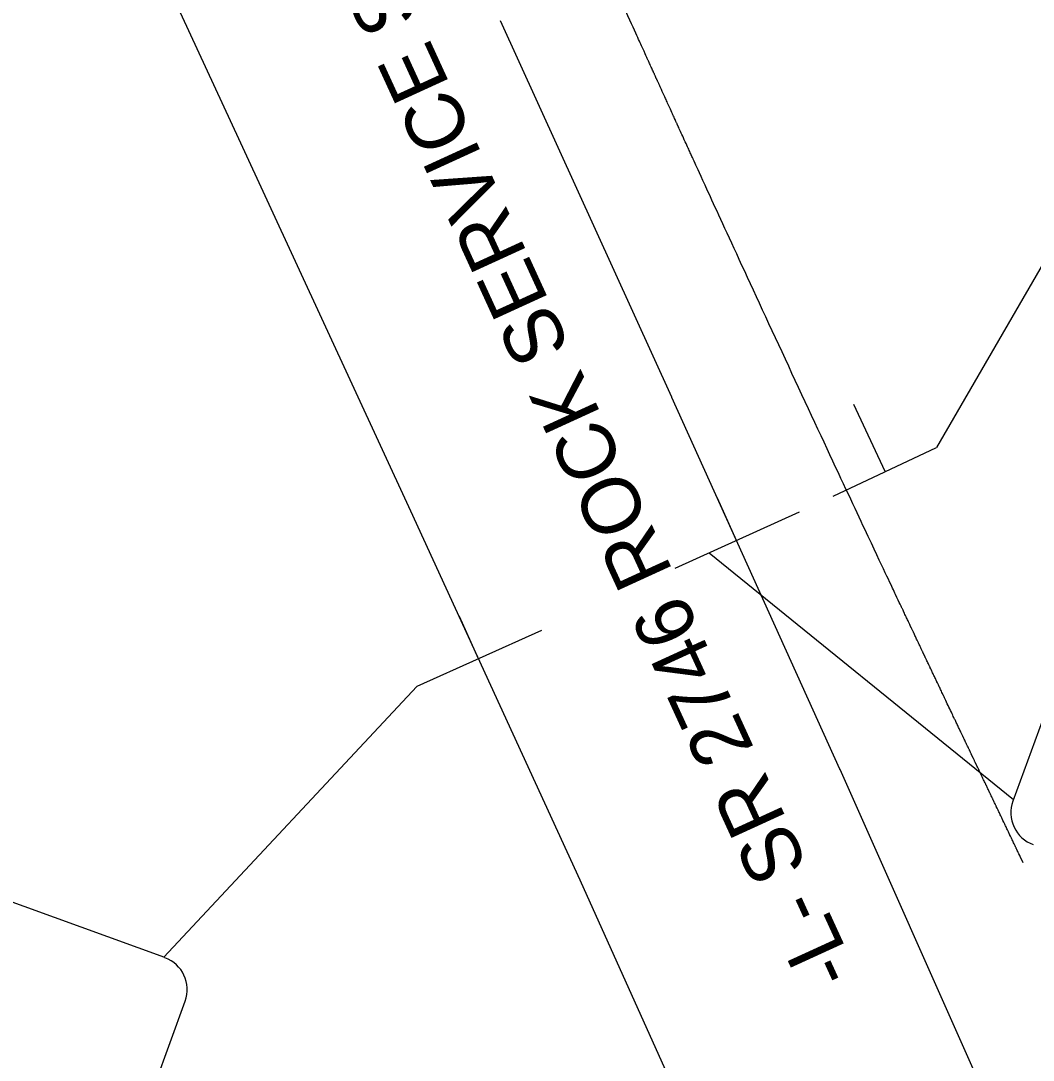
# Model space of a CAD drawing. Extents: x 2096670 to 2098561, y 684033 to 689893.
# Drawn here: x 2097860.5 to 2097982.4, y 685391.2 to 685516.3 of the extents above; entities that cross this region are included whole.
import ezdxf

# ---------------------------------------------------------------- set-up
doc = ezdxf.new("R2010")
doc.units = 0
for name, color, linetype in [('Default', 7, 'Continuous'), ('Exist Sign E Stop Ahead CELL', 7, 'Continuous'), ('Exist Support 1', 7, 'Continuous'), ('Prop DSN Text', 7, 'Continuous'), ('Prop Sign E Signal Light Ahead CELL', 7, 'Continuous'), ('Scratch_Level_4', 7, 'Continuous')]:
    doc.layers.add(name, color=color, linetype=linetype)

msp = doc.modelspace()

# ---------------------------------------------------------------- linework, layer by layer
at = {"layer": 'Exist Sign E Stop Ahead CELL'}
for p, q in [((2097999.49, 685476.17), (2097979.91, 685422.39)), ((2097979.97, 685422.55), (2097943.33, 685452.24)), ((2097908.16, 685436.19), (2097877.73, 685403.6)), ((2097877.84, 685403.56), (2097824.06, 685423.13)), ((2097860.7, 685344.55), (2097880.28, 685398.33))]:
    msp.add_line(p, q, dxfattribs=at)
for centre, start, end in [((2097983.75, 685421), 159.9971, 249.9971), ((2097876.44, 685399.72), 339.9971, 69.9971)]:
    msp.add_arc(centre, 4.08, start, end, dxfattribs=at)
at = {"layer": 'Exist Support 1'}
for p, q in [((2097946.65, 685453.76), (2097944.34, 685458.86)), ((2097954.2, 685457.17), (2097939.21, 685450.4)), ((2097915.59, 685439.55), (2097913.29, 685444.64)), ((2097923.15, 685442.96), (2097908.16, 685436.19))]:
    msp.add_line(p, q, dxfattribs=at)
at = {"layer": 'Prop DSN Text'}
for p, q in [((2097964.54, 685462.07), (2097960.76, 685470.15)), ((2097958.26, 685459.13), (2097970.73, 685464.96))]:
    msp.add_line(p, q, dxfattribs=at)
at = {"layer": 'Prop Sign E Signal Light Ahead CELL'}
msp.add_line((2098020.18, 685550.58), (2097970.73, 685464.96), dxfattribs=at)
at = {"layer": 'Scratch_Level_4'}
for p, q in [((2097938.84, 685471.03), (2097918.24, 685516.35)), ((2097959.08, 685426.23), (2097938.85, 685471.01)), ((2097979.48, 685380.36), (2097959.1, 685426.19))]:
    msp.add_line(p, q, dxfattribs=at)
msp.add_lwpolyline([(2097948.38, 685367.21), (2097927.83, 685412.88), (2097907.44, 685457.32), (2097886.75, 685502.14), (2097865.38, 685548.3)], dxfattribs=at)
for centre, start, end in [((2097933.38, 685468.54), 24.3125, 24.4514), ((2097953.62, 685423.76), 23.9717, 24.3125)]:
    msp.add_arc(centre, 6, start, end, dxfattribs=at)
for points in [[(2097937.71, 685507.83), (2097937.63, 685508), (2097937.51, 685508.26), (2097937.4, 685508.52), (2097937.32, 685508.7), (2097937.28, 685508.78), (2097937.2, 685508.95), (2097937.14, 685509.08), (2097937.08, 685509.21), (2097937.04, 685509.3), (2097937.02, 685509.34), (2097936.99, 685509.41), (2097936.98, 685509.43), (2097936.96, 685509.47), (2097936.95, 685509.49), (2097936.93, 685509.54), (2097936.92, 685509.56), (2097936.9, 685509.6), (2097936.89, 685509.62), (2097936.85, 685509.73), (2097936.81, 685509.82), (2097936.61, 685510.25), (2097936.37, 685510.77), (2097936.1, 685511.37), (2097935.96, 685511.67), (2097935.9, 685511.8), (2097935.86, 685511.89), (2097935.84, 685511.93), (2097935.2, 685513.36), (2097934.57, 685514.74), (2097932.69, 685518.88), (2097928.95, 685527.17), (2097922.74, 685541), (2097916.58, 685554.85), (2097912.91, 685563.18), (2097911.65, 685566.04), (2097911.61, 685566.12), (2097911.53, 685566.3), (2097911.42, 685566.56), (2097911.15, 685567.16), (2097910.92, 685567.68), (2097910.47, 685568.73), (2097910.16, 685569.42), (2097909.84, 685570.16), (2097909.82, 685570.2), (2097909.78, 685570.29), (2097909.72, 685570.42), (2097909.59, 685570.72), (2097909.32, 685571.33), (2097909.1, 685571.85), (2097908.64, 685572.89), (2097908.33, 685573.59), (2097908.03, 685574.29)], [(2097968.37, 685441.8), (2097968.29, 685441.97), (2097968.17, 685442.23), (2097968.05, 685442.49), (2097967.97, 685442.66), (2097967.93, 685442.74), (2097967.85, 685442.92), (2097967.78, 685443.04), (2097967.72, 685443.17), (2097967.68, 685443.26), (2097967.66, 685443.3), (2097967.63, 685443.37), (2097967.62, 685443.39), (2097967.6, 685443.43), (2097967.59, 685443.45), (2097967.57, 685443.5), (2097967.56, 685443.52), (2097967.54, 685443.56), (2097967.53, 685443.58), (2097967.48, 685443.69), (2097967.44, 685443.77), (2097967.24, 685444.2), (2097966.99, 685444.72), (2097966.71, 685445.32), (2097966.57, 685445.62), (2097966.51, 685445.75), (2097966.47, 685445.83), (2097966.45, 685445.87), (2097965.78, 685447.29), (2097965.13, 685448.66), (2097963.19, 685452.78), (2097959.32, 685461.01), (2097952.91, 685474.75), (2097946.55, 685488.52), (2097942.75, 685496.79), (2097941.45, 685499.64), (2097941.41, 685499.72), (2097941.33, 685499.89), (2097941.22, 685500.15), (2097940.94, 685500.75), (2097940.7, 685501.27), (2097940.23, 685502.31), (2097939.92, 685503), (2097939.58, 685503.73), (2097939.56, 685503.77), (2097939.52, 685503.86), (2097939.46, 685503.99), (2097939.33, 685504.29), (2097939.05, 685504.89), (2097938.81, 685505.41), (2097938.34, 685506.45), (2097938.03, 685507.14), (2097937.71, 685507.83)], [(2097981.14, 685414.96), (2097980.88, 685415.52), (2097980.61, 685416.08), (2097980.34, 685416.66), (2097980.33, 685416.68), (2097980.31, 685416.71), (2097980.29, 685416.76), (2097980.23, 685416.89), (2097980.11, 685417.13), (2097979.88, 685417.63), (2097979.68, 685418.05), (2097979.53, 685418.34), (2097979.53, 685418.36), (2097979.51, 685418.4), (2097979.48, 685418.45), (2097979.43, 685418.57), (2097979.31, 685418.82), (2097979.07, 685419.31), (2097978.87, 685419.73), (2097978.72, 685420.05), (2097978.71, 685420.08), (2097978.67, 685420.15), (2097978.62, 685420.26), (2097978.51, 685420.5), (2097978.27, 685421), (2097978.07, 685421.42), (2097977.93, 685421.72), (2097977.92, 685421.73), (2097977.9, 685421.77), (2097977.88, 685421.82), (2097977.82, 685421.94), (2097977.7, 685422.19), (2097977.6, 685422.4), (2097977.53, 685422.56), (2097977.52, 685422.58), (2097977.5, 685422.61), (2097977.48, 685422.66), (2097977.42, 685422.79), (2097977.3, 685423.03), (2097977.2, 685423.24), (2097977.12, 685423.42), (2097977.1, 685423.45), (2097977.07, 685423.52), (2097977.02, 685423.63), (2097976.9, 685423.87), (2097976.8, 685424.08), (2097976.7, 685424.29), (2097976.67, 685424.36), (2097976.6, 685424.51), (2097976.5, 685424.72), (2097976.4, 685424.93), (2097976.2, 685425.34), (2097976.06, 685425.62), (2097975.86, 685426.04), (2097975.8, 685426.18), (2097975.7, 685426.39), (2097975.66, 685426.46), (2097975.61, 685426.57), (2097975.6, 685426.6), (2097975.57, 685426.66), (2097975.56, 685426.67), (2097975.55, 685426.7), (2097975.55, 685426.7), (2097975.55, 685426.71), (2097975.54, 685426.72), (2097975.53, 685426.73), (2097975.53, 685426.75), (2097975.53, 685426.75), (2097975.52, 685426.76), (2097975.52, 685426.77), (2097975.5, 685426.8), (2097975.47, 685426.86), (2097975.45, 685426.92), (2097975.41, 685426.99), (2097975.4, 685427.02), (2097975.36, 685427.09), (2097975.35, 685427.13), (2097975.26, 685427.3), (2097975.2, 685427.44), (2097975.11, 685427.61), (2097975.1, 685427.65), (2097975.06, 685427.72), (2097975.05, 685427.75), (2097975.02, 685427.81), (2097975.01, 685427.82), (2097975, 685427.86), (2097974.97, 685427.91), (2097974.95, 685427.96), (2097974.92, 685428.03), (2097974.9, 685428.07), (2097974.87, 685428.14), (2097974.82, 685428.24), (2097974.77, 685428.35), (2097974.72, 685428.45), (2097974.7, 685428.49), (2097974.67, 685428.56), (2097974.62, 685428.66), (2097974.5, 685428.9), (2097974.4, 685429.11), (2097974.33, 685429.27), (2097974.32, 685429.29), (2097974.3, 685429.32), (2097974.28, 685429.37), (2097974.22, 685429.5), (2097974.1, 685429.74), (2097974, 685429.95), (2097973.9, 685430.16), (2097973.87, 685430.23), (2097973.8, 685430.37), (2097973.7, 685430.57), (2097973.47, 685431.06), (2097973.27, 685431.48), (2097973.01, 685432.04), (2097972.87, 685432.32), (2097972.61, 685432.87), (2097972.21, 685433.71), (2097971.81, 685434.55), (2097971.54, 685435.12), (2097971.53, 685435.14), (2097971.52, 685435.17), (2097971.49, 685435.23), (2097971.43, 685435.35), (2097971.32, 685435.59), (2097971.09, 685436.08), (2097970.89, 685436.5), (2097970.74, 685436.81), (2097970.72, 685436.85), (2097970.69, 685436.92), (2097970.64, 685437.02), (2097970.52, 685437.26), (2097970.29, 685437.75), (2097970.09, 685438.17), (2097969.94, 685438.48), (2097969.93, 685438.52), (2097969.89, 685438.59), (2097969.84, 685438.69), (2097969.73, 685438.94), (2097969.63, 685439.15), (2097969.5, 685439.43), (2097969.43, 685439.57), (2097969.36, 685439.71), (2097969.36, 685439.72), (2097969.35, 685439.74), (2097969.34, 685439.77), (2097969.31, 685439.83), (2097969.28, 685439.88), (2097969.26, 685439.92), (2097969.26, 685439.93), (2097969.25, 685439.95), (2097969.24, 685439.97), (2097969.21, 685440.04), (2097969.18, 685440.09), (2097969.16, 685440.14), (2097969.15, 685440.16), (2097969.13, 685440.19), (2097969.11, 685440.24), (2097969.05, 685440.37), (2097969, 685440.47), (2097968.9, 685440.68), (2097968.84, 685440.82), (2097968.64, 685441.24), (2097968.51, 685441.52), (2097968.37, 685441.8)]]:
    msp.add_open_spline(points, degree=3, dxfattribs=at)

# ---------------------------------------------------------------- texts
at = {"layer": 'Default'}
msp.add_text('-L- SR 2746 ROCK SERVICE STATION RD', height=7, rotation=114.6077, dxfattribs=at).set_placement((2097961.16, 685401.74))

doc.saveas('drawing.dxf')
